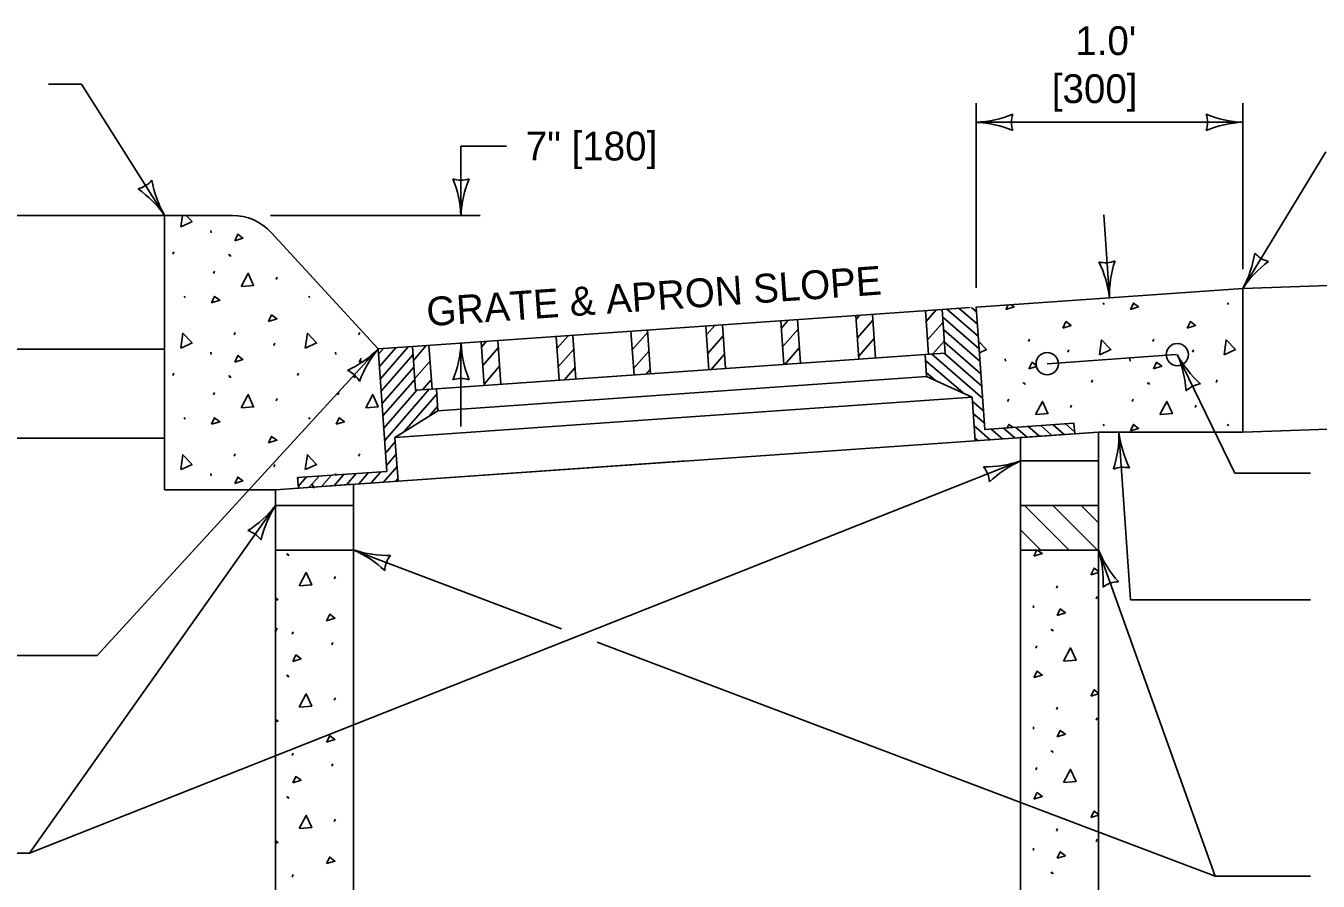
# Model space of a CAD drawing. Extents: x 49991.4 to 50048.3, y 49987.6 to 50018.3.
# Drawn here: x 50007.217 to 50009.908, y 49989.162 to 49990.944 of the extents above; entities that cross this region are included whole.
import ezdxf

# ---------------------------------------------------------------- set-up
doc = ezdxf.new("R2010")
doc.units = 0
for name, color, linetype in [('Level 1', 7, 'Continuous'), ('Level 2', 7, 'Continuous'), ('Level 3', 7, 'Continuous'), ('Level 4', 7, 'Continuous')]:
    doc.layers.add(name, color=color, linetype=linetype)

# ---------------------------------------------------------------- blocks, each defined once
blk = doc.blocks.new('REB')
at = {"layer": 'Level 1'}
blk.add_circle((0.0417, 0), 0.0417, dxfattribs=at)

msp = doc.modelspace()

# ---------------------------------------------------------------- linework, layer by layer
at = {"layer": 'Level 1'}
for p, q in [((50007.5058, 49990.5488), (50005.7794, 49990.5488)), ((50007.5058, 49989.9775), (50007.5058, 49990.5488)), ((50007.5058, 49990.5488), (50007.6466, 49990.5488)), ((50007.5396, 49990.5251), (50007.5428, 49990.5488)), ((50007.6024, 49990.5172), (50007.6029, 49990.5123)), ((50007.7285, 49990.5128), (50007.9509, 49990.2706)), ((50007.523, 49990.468), (50007.5251, 49990.4728)), ((50007.6394, 49990.468), (50007.6415, 49990.4647)), ((50007.6415, 49990.4667), (50007.6437, 49990.4635)), ((50009.7514, 49990.3965), (50011.4836, 49990.457)), ((50007.6074, 49990.4278), (50007.6096, 49990.4327)), ((50007.7384, 49990.4154), (50007.7406, 49990.4203)), ((50009.1964, 49990.3577), (50009.7514, 49990.3965)), ((50009.7514, 49990.3965), (50009.7514, 49990.0974)), ((50007.5468, 49990.3807), (50007.5489, 49990.3775)), ((50007.8061, 49990.3807), (50007.8083, 49990.3775)), ((50009.4604, 49990.3668), (50009.4626, 49990.3635)), ((50009.7197, 49990.3668), (50009.7219, 49990.3635)), ((50008.0219, 49990.2756), (50009.1254, 49990.3528)), ((50008.9455, 49990.3402), (50008.9519, 49990.2491)), ((50008.946, 49990.3323), (50008.9534, 49990.3407)), ((50008.9802, 49990.3426), (50008.9865, 49990.2516)), ((50009.0908, 49990.3503), (50009.0971, 49990.2593)), ((50009.0923, 49990.3281), (50009.113, 49990.3519)), ((50009.1836, 49990.3568), (50009.1254, 49990.3528)), ((50009.1254, 49990.3528), (50009.1317, 49990.2617)), ((50009.1254, 49990.3528), (50009.1317, 49990.2617)), ((50009.1265, 49990.3366), (50009.2025, 49990.2706)), ((50009.135, 49990.3534), (50009.2007, 49990.2963)), ((50009.1607, 49990.3552), (50009.1989, 49990.3221)), ((50009.1865, 49990.357), (50009.1971, 49990.3478)), ((50009.2142, 49990.1028), (50009.1964, 49990.3577)), ((50009.258, 49990.3527), (50009.2626, 49990.3624)), ((50008.5119, 49990.3099), (50008.5182, 49990.2188)), ((50008.6333, 49990.3184), (50008.6397, 49990.2273)), ((50008.6346, 49990.2998), (50008.6519, 49990.3197)), ((50008.668, 49990.3208), (50008.6743, 49990.2297)), ((50008.7894, 49990.3293), (50008.7958, 49990.2382)), ((50008.7904, 49990.3137), (50008.8048, 49990.3304)), ((50008.7931, 49990.2751), (50008.8252, 49990.3121)), ((50008.8241, 49990.3317), (50008.8304, 49990.2407)), ((50008.9487, 49990.2937), (50008.981, 49990.3308)), ((50009.095, 49990.2895), (50009.1272, 49990.3265)), ((50009.1283, 49990.3109), (50009.2043, 49990.2448)), ((50007.6507, 49990.3001), (50007.6529, 49990.3049)), ((50007.733, 49990.2779), (50007.7352, 49990.2828)), ((50007.91, 49990.3001), (50007.9122, 49990.3049)), ((50008.165, 49990.2856), (50008.1714, 49990.1946)), ((50008.1657, 49990.2747), (50008.1759, 49990.2864)), ((50008.1997, 49990.288), (50008.206, 49990.197)), ((50008.3211, 49990.2965), (50008.3275, 49990.2055)), ((50008.323, 49990.2718), (50008.3461, 49990.2983)), ((50008.3558, 49990.299), (50008.3621, 49990.2079)), ((50008.4772, 49990.3074), (50008.4836, 49990.2164)), ((50008.4799, 49990.2685), (50008.5122, 49990.3056)), ((50008.6373, 49990.2611), (50008.6695, 49990.2983)), ((50008.9518, 49990.2555), (50008.9837, 49990.2922)), ((50009.1055, 49990.2599), (50009.1299, 49990.2879)), ((50009.1301, 49990.2851), (50009.2061, 49990.2191)), ((50009.3051, 49990.2861), (50009.3072, 49990.291)), ((50009.5644, 49990.2861), (50009.5665, 49990.291)), ((50007.5058, 49990.2704), (50005.8228, 49990.2704)), ((50007.6024, 49990.2643), (50007.6029, 49990.2594)), ((50007.8617, 49990.2643), (50007.8623, 49990.2594)), ((50008.0219, 49990.2756), (50007.9509, 49990.2706)), ((50007.9509, 49990.2706), (50007.9687, 49990.0157)), ((50007.9516, 49990.2599), (50007.9616, 49990.2714)), ((50007.9534, 49990.2342), (50007.9873, 49990.2732)), ((50007.9552, 49990.2084), (50008.0131, 49990.275)), ((50007.957, 49990.1827), (50008.0231, 49990.2587)), ((50008.0219, 49990.2756), (50008.0282, 49990.1846)), ((50008.0282, 49990.1846), (50008.0219, 49990.2756)), ((50008.0239, 49990.2467), (50008.0507, 49990.2776)), ((50008.0565, 49990.278), (50008.0628, 49990.187)), ((50008.1684, 49990.2361), (50008.2007, 49990.2732)), ((50008.3257, 49990.2331), (50008.3579, 49990.2701)), ((50008.4826, 49990.2299), (50008.5149, 49990.267)), ((50008.6444, 49990.2276), (50008.6723, 49990.2596)), ((50008.7974, 49990.2383), (50008.8279, 49990.2735)), ((50009.1317, 49990.2617), (50009.0898, 49990.2588)), ((50009.0898, 49990.2588), (50009.093, 49990.2133)), ((50009.1036, 49990.2598), (50009.2097, 49990.1676)), ((50009.1294, 49990.2616), (50009.2079, 49990.1933)), ((50009.344, 49990.24), (50009.6126, 49990.2588)), ((50009.3873, 49990.2639), (50009.3895, 49990.2688)), ((50009.6467, 49990.2639), (50009.6488, 49990.2688)), ((50007.9111, 49990.2432), (50007.9149, 49990.2512)), ((50007.9173, 49990.2452), (50007.9111, 49990.2432)), ((50007.9588, 49990.1569), (50008.0249, 49990.2329)), ((50008.0266, 49990.2081), (50008.0578, 49990.244)), ((50008.1711, 49990.1975), (50008.2034, 49990.2346)), ((50008.3387, 49990.2063), (50008.3606, 49990.2315)), ((50008.9846, 49990.2514), (50008.9864, 49990.2535)), ((50009.0907, 49990.2468), (50009.1688, 49990.179)), ((50009.2567, 49990.2503), (50009.2573, 49990.2455)), ((50009.3216, 49990.2341), (50009.3061, 49990.2293)), ((50009.516, 49990.2503), (50009.5166, 49990.2455)), ((50007.523, 49990.2151), (50007.5251, 49990.22)), ((50007.6394, 49990.2151), (50007.6415, 49990.2118)), ((50007.6415, 49990.2139), (50007.6437, 49990.2106)), ((50007.7823, 49990.2151), (50007.7844, 49990.22)), ((50007.8987, 49990.2151), (50007.9008, 49990.2118)), ((50007.9008, 49990.2139), (50007.903, 49990.2106)), ((50007.9606, 49990.1312), (50008.0267, 49990.2071)), ((50008.0433, 49990.1856), (50008.0605, 49990.2054)), ((50008.5087, 49990.2182), (50008.5176, 49990.2284)), ((50009.0925, 49990.2211), (50009.1107, 49990.2053)), ((50009.093, 49990.2133), (50009.1875, 49990.1705)), ((50009.4366, 49990.2011), (50009.4388, 49990.206)), ((50009.6959, 49990.2011), (50009.6981, 49990.206)), ((50007.6074, 49990.175), (50007.6096, 49990.1798)), ((50007.8667, 49990.175), (50007.8689, 49990.1798)), ((50007.9624, 49990.1054), (50008.0314, 49990.1848)), ((50007.9642, 49990.0797), (50008.0572, 49990.1866)), ((50008.0044, 49990.0981), (50008.0727, 49990.1766)), ((50008.0719, 49990.1876), (50008.0282, 49990.1846)), ((50008.0751, 49990.1421), (50008.0719, 49990.1876)), ((50009.2937, 49990.2011), (50009.2959, 49990.1979)), ((50009.2959, 49990.1999), (50009.298, 49990.1966)), ((50009.553, 49990.2011), (50009.5552, 49990.1979)), ((50009.5552, 49990.1999), (50009.5573, 49990.1966)), ((50007.7384, 49990.1625), (50007.7406, 49990.1674)), ((50007.9857, 49990.0864), (50009.1875, 49990.1705)), ((50008.0571, 49990.1309), (50008.0745, 49990.1509)), ((50009.1875, 49990.1705), (50009.1939, 49990.0794)), ((50009.1881, 49990.1622), (50009.2115, 49990.1418)), ((50009.2617, 49990.161), (50009.2639, 49990.1659)), ((50009.3928, 49990.1486), (50009.3949, 49990.1534)), ((50009.5211, 49990.161), (50009.5232, 49990.1659)), ((50009.6521, 49990.1486), (50009.6542, 49990.1534)), ((50009.7514, 49990.0974), (50011.4941, 49990.1582)), ((50007.5468, 49990.1279), (50007.5489, 49990.1246)), ((50007.8061, 49990.1279), (50007.8083, 49990.1246)), ((50007.9857, 49990.0864), (50008.0751, 49990.1421)), ((50009.1899, 49990.1364), (50009.2133, 49990.1161)), ((50009.1917, 49990.1106), (50009.2251, 49990.0816)), ((50009.1939, 49990.0794), (50009.4015, 49990.0939)), ((50009.3999, 49990.1158), (50009.2142, 49990.1028)), ((50009.2275, 49990.1037), (50009.2509, 49990.0834)), ((50009.2532, 49990.1055), (50009.2766, 49990.0852)), ((50009.279, 49990.1073), (50009.3024, 49990.087)), ((50009.3047, 49990.1091), (50009.3281, 49990.0888)), ((50009.3305, 49990.1109), (50009.3539, 49990.0906)), ((50009.3562, 49990.1127), (50009.3796, 49990.0924)), ((50009.382, 49990.1145), (50009.4012, 49990.0978)), ((50009.4015, 49990.0939), (50009.3999, 49990.1158)), ((50009.4509, 49990.0974), (50009.7514, 49990.0974)), ((50009.4604, 49990.1139), (50009.4626, 49990.1107)), ((50009.7197, 49990.1139), (50009.7219, 49990.1107)), ((50007.5058, 49990.0848), (50006.9652, 49990.0848)), ((50007.966, 49990.0539), (50007.9863, 49990.0773)), ((50007.9921, 49989.9954), (50007.9857, 49990.0864)), ((50007.9921, 49989.9954), (50009.1939, 49990.0794)), ((50009.1935, 49990.0849), (50009.1994, 49990.0798)), ((50007.6507, 49990.0472), (50007.6529, 49990.0521)), ((50007.91, 49990.0472), (50007.9122, 49990.0521)), ((50007.9678, 49990.0282), (50007.9881, 49990.0515)), ((50007.733, 49990.025), (50007.7352, 49990.0299)), ((50007.9687, 49990.0157), (50007.7829, 49990.0027)), ((50007.9359, 49989.9915), (50007.9562, 49990.0148)), ((50007.9617, 49989.9933), (50007.9899, 49990.0258)), ((50007.9921, 49989.9954), (50008.593, 49990.0374)), ((50008.593, 49990.0374), (50008.593, 49990.0374)), ((50008.593, 49990.0374), (50008.593, 49990.0374)), ((50009.2884, 49988.8071), (50009.2884, 49990.0374)), ((50009.2884, 49990.0374), (50009.4509, 49990.0374)), ((50009.4509, 49988.8071), (50009.4509, 49990.0374)), ((50007.6024, 49990.0114), (50007.6029, 49990.0065)), ((50007.7829, 49990.0027), (50007.7845, 49989.9809)), ((50007.7831, 49990.0009), (50007.7848, 49990.0028)), ((50007.7843, 49989.9839), (50007.8017, 49990.004)), ((50007.7845, 49989.9809), (50007.9921, 49989.9954)), ((50007.8072, 49989.9825), (50007.8275, 49990.0058)), ((50007.8135, 49989.9881), (50007.8172, 49989.9808)), ((50007.8329, 49989.9843), (50007.8532, 49990.0076)), ((50007.8587, 49989.9861), (50007.879, 49990.0094)), ((50007.8617, 49990.0114), (50007.8621, 49990.0082)), ((50007.8844, 49989.9879), (50007.9047, 49990.0112)), ((50007.9102, 49989.9897), (50007.9305, 49990.013)), ((50007.9874, 49989.9951), (50007.9917, 49990)), ((50007.7369, 49989.9775), (50007.5058, 49989.9775)), ((50007.7845, 49989.9809), (50007.7845, 49989.9809)), ((50007.8993, 49989.9447), (50007.7369, 49989.9447)), ((50007.7369, 49989.9447), (50007.7369, 49989.8519)), ((50007.8993, 49989.8519), (50007.8993, 49989.9447)), ((50009.297, 49989.9447), (50009.3897, 49989.8519)), ((50009.356, 49989.9447), (50009.4487, 49989.8519)), ((50009.415, 49989.9447), (50009.4509, 49989.9088)), ((50009.2884, 49989.8942), (50009.3307, 49989.8519)), ((50007.7369, 49988.8071), (50007.7369, 49989.8519)), ((50007.7369, 49989.8519), (50007.8993, 49989.8519)), ((50007.8993, 49988.8071), (50007.8993, 49989.8519)), ((50009.3165, 49989.839), (50009.3227, 49989.8519)), ((50007.7602, 49989.8445), (50007.7624, 49989.8413)), ((50007.7624, 49989.8433), (50007.7646, 49989.8401)), ((50009.4509, 49989.8052), (50009.4352, 49989.8003)), ((50007.8593, 49989.792), (50007.8615, 49989.7968)), ((50009.3636, 49989.7724), (50009.3658, 49989.7773)), ((50009.4459, 49989.7502), (50009.4481, 49989.7551)), ((50009.3153, 49989.7366), (50009.3159, 49989.7318)), ((50007.7369, 49989.6815), (50007.7405, 49989.6888)), ((50007.7716, 49989.6767), (50007.7738, 49989.6815)), ((50009.3523, 49989.6874), (50009.3544, 49989.6842)), ((50009.3544, 49989.6862), (50009.3566, 49989.683)), ((50007.8539, 49989.6545), (50007.8561, 49989.6593)), ((50009.3203, 49989.6473), (50009.3225, 49989.6522)), ((50007.7602, 49989.5917), (50007.7624, 49989.5884)), ((50007.7624, 49989.5904), (50007.7646, 49989.5872)), ((50007.8593, 49989.5391), (50007.8615, 49989.544)), ((50009.4509, 49989.5523), (50009.4352, 49989.5474)), ((50009.3636, 49989.5196), (50009.3658, 49989.5244)), ((50009.4459, 49989.4974), (50009.4481, 49989.5022)), ((50009.3153, 49989.4838), (50009.3159, 49989.4789)), ((50007.7716, 49989.4238), (50007.7738, 49989.4287)), ((50009.3523, 49989.4346), (50009.3544, 49989.4313)), ((50009.3544, 49989.4333), (50009.3566, 49989.4301)), ((50007.8539, 49989.4016), (50007.8561, 49989.4065)), ((50009.3203, 49989.3944), (50009.3225, 49989.3993)), ((50007.7602, 49989.3388), (50007.7624, 49989.3356)), ((50007.7624, 49989.3376), (50007.7646, 49989.3343)), ((50007.8593, 49989.2862), (50007.8615, 49989.2911)), ((50009.4509, 49989.2995), (50009.4352, 49989.2946)), ((50009.3636, 49989.2667), (50009.3658, 49989.2716)), ((50009.4459, 49989.2445), (50009.4481, 49989.2494)), ((50009.3153, 49989.2309), (50009.3159, 49989.226)), ((50009.3523, 49989.1817), (50009.3544, 49989.1785)), ((50009.3544, 49989.1805), (50009.3566, 49989.1772)), ((50007.7716, 49989.1709), (50007.7738, 49989.1758))]:
    msp.add_line(p, q, dxfattribs=at)
for points in [[(50007.5509, 49990.5488), (50007.5632, 49990.5361), (50007.5401, 49990.5253)], [(50007.6518, 49990.4961), (50007.6583, 49990.5096), (50007.6691, 49990.5015), (50007.6518, 49990.4961)], [(50007.6653, 49990.4008), (50007.68, 49990.4284), (50007.6913, 49990.4029), (50007.6659, 49990.4008)], [(50007.6036, 49990.3667), (50007.6101, 49990.3802), (50007.6209, 49990.3721), (50007.6036, 49990.3667)], [(50009.5173, 49990.3527), (50009.5238, 49990.3662), (50009.5346, 49990.3581), (50009.5173, 49990.3527)], [(50007.7223, 49990.328), (50007.7288, 49990.3415), (50007.7396, 49990.3334), (50007.7223, 49990.328)], [(50009.269, 49990.3628), (50009.2753, 49990.3581), (50009.258, 49990.3527)], [(50009.3766, 49990.314), (50009.3831, 49990.3275), (50009.3939, 49990.3194), (50009.3766, 49990.314)], [(50009.6359, 49990.314), (50009.6424, 49990.3275), (50009.6533, 49990.3194), (50009.6359, 49990.314)], [(50007.5396, 49990.2723), (50007.5438, 49990.3032), (50007.5632, 49990.2832), (50007.5401, 49990.2725)], [(50007.7989, 49990.2723), (50007.8032, 49990.3032), (50007.8225, 49990.2832), (50007.7994, 49990.2725)], [(50009.2014, 49990.2859), (50009.2176, 49990.2692), (50009.203, 49990.2625)], [(50009.4532, 49990.2583), (50009.4575, 49990.2893), (50009.4769, 49990.2692), (50009.4537, 49990.2585)], [(50009.7125, 49990.2583), (50009.7168, 49990.2893), (50009.7362, 49990.2692), (50009.713, 49990.2585)], [(50007.6518, 49990.2432), (50007.6583, 49990.2568), (50007.6691, 49990.2486), (50007.6518, 49990.2432)], [(50007.9256, 49990.2508), (50007.9284, 49990.2486), (50007.9215, 49990.2465)], [(50009.3061, 49990.2293), (50009.3126, 49990.2428), (50009.3211, 49990.2364)], [(50009.5655, 49990.2293), (50009.572, 49990.2428), (50009.5828, 49990.2347), (50009.5655, 49990.2293)], [(50007.6653, 49990.1479), (50007.68, 49990.1755), (50007.6913, 49990.1501), (50007.6659, 49990.1479)], [(50007.9247, 49990.1479), (50007.9393, 49990.1755), (50007.9506, 49990.1501), (50007.9252, 49990.1479)], [(50009.3197, 49990.1339), (50009.3343, 49990.1615), (50009.3457, 49990.1361), (50009.3202, 49990.1339)], [(50009.579, 49990.1339), (50009.5936, 49990.1615), (50009.605, 49990.1361), (50009.5795, 49990.1339)], [(50007.6036, 49990.1138), (50007.6101, 49990.1273), (50007.6209, 49990.1192), (50007.6036, 49990.1138)], [(50007.8629, 49990.1138), (50007.8694, 49990.1273), (50007.8803, 49990.1192), (50007.8629, 49990.1138)], [(50009.261, 49990.1061), (50009.2645, 49990.1134), (50009.2731, 49990.1069)], [(50009.5173, 49990.0998), (50009.5238, 49990.1134), (50009.5346, 49990.1052), (50009.5173, 49990.0998)], [(50007.7223, 49990.0751), (50007.7288, 49990.0886), (50007.7396, 49990.0805), (50007.7223, 49990.0751)], [(50007.5396, 49990.0194), (50007.5438, 49990.0503), (50007.5632, 49990.0303), (50007.5401, 49990.0196)], [(50007.7989, 49990.0194), (50007.8032, 49990.0503), (50007.8225, 49990.0303), (50007.7994, 49990.0196)], [(50007.6518, 49989.9904), (50007.6583, 49990.0039), (50007.6691, 49989.9958), (50007.6518, 49989.9904)], [(50009.3238, 49989.8519), (50009.3339, 49989.8444), (50009.3165, 49989.839)], [(50007.7862, 49989.7774), (50007.8008, 49989.805), (50007.8122, 49989.7795), (50007.7868, 49989.7774)], [(50009.4352, 49989.8003), (50009.4417, 49989.8139), (50009.4509, 49989.807)], [(50007.7369, 49989.7524), (50007.7418, 49989.7487), (50007.7369, 49989.7471)], [(50007.8432, 49989.7046), (50007.8497, 49989.7181), (50007.8605, 49989.71), (50007.8432, 49989.7046)], [(50009.3647, 49989.7156), (50009.3712, 49989.7291), (50009.3821, 49989.721), (50009.3647, 49989.7156)], [(50009.3783, 49989.6202), (50009.3929, 49989.6479), (50009.4043, 49989.6224), (50009.3788, 49989.6202)], [(50007.7727, 49989.6198), (50007.7792, 49989.6334), (50007.79, 49989.6252), (50007.7727, 49989.6198)], [(50009.3165, 49989.5861), (50009.323, 49989.5997), (50009.3339, 49989.5916), (50009.3165, 49989.5861)], [(50009.4352, 49989.5474), (50009.4417, 49989.561), (50009.4509, 49989.5541)], [(50007.7862, 49989.5245), (50007.8008, 49989.5521), (50007.8122, 49989.5267), (50007.7868, 49989.5245)], [(50007.7369, 49989.4995), (50007.7418, 49989.4958), (50007.7369, 49989.4942)], [(50009.3647, 49989.4627), (50009.3712, 49989.4763), (50009.3821, 49989.4681), (50009.3647, 49989.4627)], [(50007.8432, 49989.4517), (50007.8497, 49989.4652), (50007.8605, 49989.4571), (50007.8432, 49989.4517)], [(50009.3783, 49989.3674), (50009.3929, 49989.395), (50009.4043, 49989.3695), (50009.3788, 49989.3674)], [(50007.7727, 49989.367), (50007.7792, 49989.3805), (50007.79, 49989.3724), (50007.7727, 49989.367)], [(50009.3165, 49989.3333), (50009.323, 49989.3468), (50009.3339, 49989.3387), (50009.3165, 49989.3333)], [(50007.7862, 49989.2716), (50007.8008, 49989.2992), (50007.8122, 49989.2738), (50007.7868, 49989.2716)], [(50009.4352, 49989.2946), (50009.4417, 49989.3081), (50009.4509, 49989.3012)], [(50007.7369, 49989.2466), (50007.7418, 49989.2429), (50007.7369, 49989.2414)], [(50007.8432, 49989.1988), (50007.8497, 49989.2123), (50007.8605, 49989.2042), (50007.8432, 49989.1988)], [(50009.3647, 49989.2098), (50009.3712, 49989.2234), (50009.3821, 49989.2153), (50009.3647, 49989.2098)]]:
    msp.add_lwpolyline(points, dxfattribs=at)
for points in [[(50009.7514, 49990.3965), (50009.1964, 49990.3577), (50009.2142, 49990.1028), (50009.3999, 49990.1158), (50009.4015, 49990.0939), (50009.4509, 49990.0974), (50009.7514, 49990.0974)], [(50009.7514, 49990.0974), (50009.7514, 49990.3965), (50009.1964, 49990.3577), (50009.2142, 49990.1028), (50009.3999, 49990.1158), (50009.4015, 49990.0939), (50009.4509, 49990.0974)], [(50009.2884, 49990.086), (50009.4509, 49990.0974), (50009.4509, 49990.0374), (50009.2884, 49990.0374)], [(50009.4509, 49989.9447), (50009.4509, 49990.0374), (50009.2884, 49990.0374), (50009.2884, 49989.9447)], [(50009.2884, 49990.0374), (50009.4509, 49990.0374), (50009.4509, 49989.9447), (50009.2884, 49989.9447)], [(50007.8993, 49989.9889), (50007.8993, 49989.9447), (50007.7369, 49989.9447), (50007.7369, 49989.9775)], [(50007.8993, 49989.9447), (50007.7369, 49989.9447), (50007.7369, 49989.8519), (50007.8993, 49989.8519)], [(50009.2884, 49989.9447), (50009.4509, 49989.9447), (50009.4509, 49989.8519), (50009.2884, 49989.8519)]]:
    msp.add_lwpolyline(points, close=True, dxfattribs=at)
msp.add_arc((50007.6466, 49990.4375), 0.1113, 42.5595, 90, dxfattribs=at)
at = {"layer": 'Level 3'}
for p, q in [((50007.3329, 49990.8218), (50007.264, 49990.8218)), ((50007.5058, 49990.5488), (50007.3329, 49990.8218)), ((50009.1964, 49990.3977), (50009.1964, 49990.7827)), ((50009.7514, 49990.4365), (50009.7514, 49990.7827)), ((50009.1964, 49990.7427), (50009.7514, 49990.7427)), ((50008.1231, 49990.6932), (50008.1231, 49990.5488)), ((50008.1231, 49990.6932), (50008.2181, 49990.6932)), ((50009.7514, 49990.3965), (50009.9242, 49990.6813)), ((50007.7266, 49990.5488), (50008.1631, 49990.5488)), ((50009.4618, 49990.5502), (50009.4739, 49990.3771)), ((50008.1231, 49990.2827), (50008.1231, 49990.1092)), ((50007.9509, 49990.2706), (50007.3651, 49989.6325)), ((50009.6151, 49990.2589), (50009.7351, 49990.0118)), ((50009.4934, 49990.0974), (50009.5179, 49989.7482)), ((50009.2884, 49990.0374), (50007.2241, 49989.2206)), ((50009.7351, 49990.0118), (50009.8927, 49990.0118)), ((50007.7369, 49989.9447), (50007.2241, 49989.2206)), ((50007.8993, 49989.8519), (50008.3323, 49989.688)), ((50009.4509, 49989.8519), (50009.694, 49989.1726)), ((50009.5179, 49989.7482), (50009.8927, 49989.7482)), ((50008.4071, 49989.6597), (50009.694, 49989.1726)), ((50007.3651, 49989.6325), (50006.6868, 49989.6325)), ((50007.2241, 49989.2206), (50007.1063, 49989.2206)), ((50009.694, 49989.1726), (50009.8927, 49989.1726))]:
    msp.add_line(p, q, dxfattribs=at)
for centre, radius, start, end in [((50009.1849, 49990.9754), 0.233, 272.8273, 292.0772), ((50009.1872, 49990.5205), 0.2223, 67.456, 87.6395), ((50009.3246, 49990.7427), 0.0548, 162.1388, 197.8612), ((50009.7606, 49990.9648), 0.2223, 247.456, 267.6395), ((50009.6232, 49990.7427), 0.0548, 342.1388, 17.8612), ((50009.7629, 49990.51), 0.233, 92.8273, 112.0772), ((50007.4372, 49990.6571), 0.0548, 284.4928, 320.2152), ((50007.6984, 49990.6599), 0.2223, 189.81, 209.9935), ((50008.1231, 49990.677), 0.0548, 252.1388, 287.8612), ((50007.8904, 49990.5373), 0.233, 2.8273, 22.0772), ((50008.3453, 49990.5396), 0.2223, 157.456, 177.6395), ((50007.3154, 49990.4145), 0.233, 35.1813, 54.4312), ((50009.4649, 49990.505), 0.0548, 256.1388, 291.8612), ((50009.2425, 49990.3494), 0.233, 6.8273, 26.0772), ((50009.6961, 49990.3835), 0.2223, 161.456, 181.6395), ((50009.5465, 49990.5075), 0.233, 331.574, 350.8239), ((50009.9365, 49990.2735), 0.2223, 126.2027, 146.3862), ((50009.8179, 49990.5062), 0.0548, 220.8855, 256.6079), ((50007.901, 49990.2918), 0.2223, 337.456, 357.6395), ((50008.3559, 49990.2942), 0.233, 182.8273, 202.0772), ((50007.7934, 49990.4276), 0.2223, 294.9066, 315.0901), ((50008.1301, 49990.1217), 0.233, 140.2779, 159.5278), ((50009.4113, 49990.1701), 0.2223, 3.3595, 23.543), ((50009.8194, 49990.3709), 0.233, 208.7308, 227.9807), ((50007.8642, 49990.1762), 0.0548, 29.5894, 65.3118), ((50008.1231, 49990.1545), 0.0548, 72.1388, 107.8612), ((50009.6711, 49990.1436), 0.0548, 98.0423, 133.7647), ((50009.2712, 49990.091), 0.2223, 341.456, 1.6395), ((50009.7248, 49990.1251), 0.233, 186.8273, 206.0772), ((50009.2152, 49990.2473), 0.2223, 269.0437, 289.2272), ((50009.1692, 49989.9902), 0.0548, 3.7265, 39.4488), ((50009.3847, 49989.8252), 0.233, 114.415, 133.6648), ((50009.5024, 49989.9695), 0.0548, 76.1388, 111.8612), ((50007.5609, 49990.0805), 0.2223, 302.1523, 322.3358), ((50007.9334, 49989.8196), 0.233, 147.5236, 166.7734), ((50007.6628, 49989.84), 0.0548, 36.8351, 72.5574), ((50007.8121, 49989.6474), 0.2223, 46.7234, 66.9069), ((50007.971, 49990.0737), 0.233, 252.0947, 271.3445), ((50009.2387, 49989.7857), 0.2223, 357.1445, 17.328), ((50009.6661, 49989.9412), 0.233, 202.5158, 221.7656), ((50008.0192, 49989.8066), 0.0548, 141.4062, 177.1285), ((50009.4941, 49989.7312), 0.0548, 91.8273, 127.5496)]:
    msp.add_arc(centre, radius, start, end, dxfattribs=at)
at = {"layer": 'Level 4'}
for p, q in [((50008.0719, 49990.1876), (50009.0898, 49990.2588)), ((50008.0751, 49990.1421), (50009.093, 49990.2133))]:
    msp.add_line(p, q, dxfattribs=at)

# ---------------------------------------------------------------- block references
at = {"layer": 'Level 1', "xscale": 0.5563768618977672, "yscale": 0.5563768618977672}
for p in [(50009.3209, 49990.24), (50009.5919, 49990.2589)]:
    msp.add_blockref('REB', p, dxfattribs=at)

# ---------------------------------------------------------------- texts
at = {"layer": 'Level 2'}
for s, p in [("1.0'", (50009.4026, 49990.8827)), ('[300]', (50009.3537, 49990.7827)), ('7" [180]', (50008.2581, 49990.6632))]:
    msp.add_text(s, height=0.06, dxfattribs=at).set_placement(p)
msp.add_text('GRATE & APRON SLOPE', height=0.06, rotation=4, dxfattribs=at).set_placement((50008.0533, 49990.3179))

doc.saveas('drawing.dxf')
